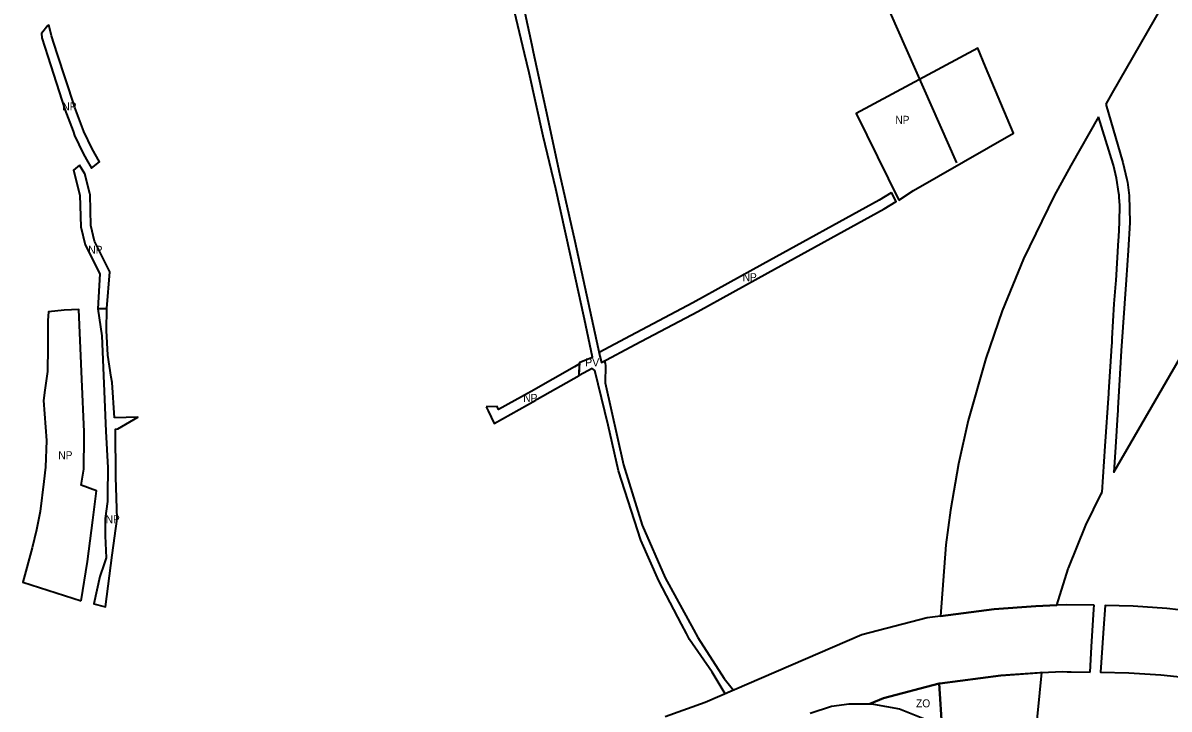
# Model space of a CAD drawing. Extents: x -650276 to -642489, y -1074311 to -1066720.
# Drawn here: x -649415 to -647696, y -1069108 to -1068079 of the extents above; entities that cross this region are included whole.
import ezdxf

# ---------------------------------------------------------------- set-up
doc = ezdxf.new("R2010")
doc.units = 0
doc.header["$LTSCALE"] = 4.8
for name, color, linetype, lineweight in [('15', 7, 'Continuous', 35), ('24', 7, 'Continuous', 35), ('25', 7, 'Continuous', 35), ('42', 7, 'Continuous', 35), ('48', 7, 'Continuous', 35), ('54', 7, 'Continuous', 35)]:
    doc.layers.add(name, color=color, linetype=linetype, lineweight=lineweight)
doc.layers.add('62', color=7, linetype='Continuous')

msp = doc.modelspace()

# ---------------------------------------------------------------- linework, layer by layer
at = {"layer": '15'}
for points in [[(-648668.92, -1068032.96), (-648651.89, -1068111.95), (-648649.74, -1068121.95), (-648644.73, -1068145.27), (-648630.99, -1068209.19), (-648610.14, -1068304.32), (-648587.39, -1068405.82), (-648559.91, -1068532.62), (-648549.84, -1068578.65), (-648547.25, -1068588.14), (-648542.93, -1068586.13), (-648541.74, -1068589.27)], [(-648349.419, -1069079.223), (-648362.06, -1069084.664), (-648381.44, -1069052.48), (-648415.29, -1069003.16), (-648419.78, -1068994.25), (-648427.21, -1068980.13), (-648461.22, -1068915.44), (-648488.09, -1068854.16), (-648521.92, -1068750.34), (-648537.29, -1068681.95), (-648557.4, -1068599.9), (-648559.44, -1068598.37), (-648561.49, -1068596.84), (-648580.66, -1068607.64), (-648579.97, -1068587.39), (-648560.79, -1068580.12), (-648572.95, -1068522.97), (-648573.96, -1068518.34), (-648594.38, -1068425.02), (-648615.87, -1068327.3), (-648634.84, -1068248.76), (-648655.88, -1068153.63), (-648662.71, -1068124.76), (-648677.61, -1068061.74)], [(-648541.74, -1068589.27), (-648541.25, -1068592.3), (-648541.89, -1068618.64), (-648514.35, -1068741.53), (-648486.25, -1068831.83), (-648451.76, -1068910.91), (-648409.15, -1068988.44), (-648402.76, -1069000.2), (-648363.11, -1069061.72), (-648349.419, -1069079.223)]]:
    msp.add_lwpolyline(points, dxfattribs=at)
at = {"layer": '24'}
for points in [[(-647864.531, -1068951.823), (-647895.901, -1068953.392), (-647958.168, -1068957.73), (-648038.596, -1068968.281), (-648038.759, -1068968.54)], [(-647808.28, -1068952.066), (-647850.043, -1068951.098), (-647864.531, -1068951.823)], [(-647814.401, -1069052.246), (-647812.34, -1069014.54), (-647808.67, -1068958.06), (-647808.28, -1068952.066)], [(-647629.424, -1068964.608), (-647699.561, -1068956.635), (-647749.978, -1068953.416), (-647792.01, -1068952.442), (-647794.21, -1068986.12), (-647796.13, -1069015.57), (-647798.631, -1069052.508), (-647756.441, -1069053.207), (-647708.401, -1069056.275), (-647511.94, -1069076.703)], [(-648038.759, -1068968.54), (-648038.746, -1068968.301), (-648058.764, -1068970.927), (-648156.739, -1068996.273), (-648392.002, -1069097.554), (-648451.865, -1069119.456)], [(-648040.705, -1069069.547), (-648039.666, -1069069.279), (-647948.18, -1069057.276), (-647886.615, -1069053.052), (-647856.541, -1069051.548), (-647848.615, -1069051.679), (-647842.888, -1069051.774), (-647814.401, -1069052.246)], [(-648234.22, -1069113.6), (-648202.46, -1069103.3), (-648175.65, -1069099.64), (-648144.866, -1069099.987), (-648124.327, -1069091.181), (-648040.705, -1069069.547)]]:
    msp.add_lwpolyline(points, dxfattribs=at)
at = {"layer": '25'}
msp.add_line((-648038.596, -1068968.281), (-647958.168, -1068957.73), dxfattribs=at)
for points in [[(-647685.819, -1068016.861), (-647781.346, -1068183.485), (-647791.055, -1068200.507)], [(-647791.055, -1068200.507), (-647765.22, -1068287.94), (-647759.412, -1068313.436)], [(-647801.797, -1068219.34), (-647843.6, -1068292.629), (-647868.214, -1068337.803), (-647914.339, -1068432.512), (-647946.187, -1068510.254), (-647971.074, -1068581.98), (-647997.27, -1068674.747), (-648011.775, -1068739.718), (-648023.914, -1068809.332), (-648030.73, -1068861.213), (-648038.596, -1068968.281)], [(-647771.413, -1068334.626), (-647774.94, -1068311.47), (-647779.55, -1068292.23), (-647780.07, -1068290.53), (-647801.797, -1068219.34)], [(-647768.02, -1068570.36), (-647770.94, -1068622.47), (-647772.85, -1068656.41), (-647773.08, -1068660.57), (-647773.4, -1068665.71), (-647776.5, -1068714.8), (-647778.95, -1068752.433), (-647675.054, -1068572.919), (-647535.844, -1068336.279), (-647464.94, -1068215.752)], [(-647759.412, -1068313.436), (-647758.45, -1068317.66), (-647756.09, -1068337.61), (-647754.99, -1068378.21), (-647757.41, -1068419.98), (-647760.22, -1068463.96), (-647768.02, -1068570.36)], [(-647796.173, -1068782.191), (-647791.77, -1068713.23), (-647786.47, -1068634.37), (-647786.32, -1068632.19), (-647781.85, -1068562.97), (-647781.55, -1068558.38), (-647781.13, -1068551.88), (-647778.24, -1068499.95), (-647775.82, -1068469.74), (-647775.52, -1068464.97), (-647771.74, -1068404.5), (-647771.47, -1068400.07), (-647770.12, -1068377.5), (-647769.92, -1068352.1), (-647770.81, -1068340.29), (-647771.05, -1068337.01), (-647771.413, -1068334.626)], [(-647846.989, -1068896.545), (-647820.883, -1068832.117), (-647797.632, -1068784.713), (-647796.173, -1068782.191)], [(-647958.168, -1068957.73), (-647895.901, -1068953.392), (-647864.531, -1068951.823), (-647847.197, -1068897.199), (-647847.034, -1068896.687), (-647846.989, -1068896.545)], [(-647948.18, -1069057.276), (-648039.666, -1069069.279), (-648040.705, -1069069.548), (-648036.291, -1069139.458)], [(-647886.615, -1069053.052), (-647889.927, -1069053.218), (-647948.18, -1069057.276)], [(-647893.553, -1069279.017), (-647896.67, -1069213.573), (-647896.362, -1069149.171), (-647886.615, -1069053.052)]]:
    msp.add_lwpolyline(points, dxfattribs=at)
at = {"layer": '42'}
msp.add_lwpolyline([(-648100.37, -1069107.1), (-648065.16, -1069121.12), (-648048.06, -1069130.81), (-648036.291, -1069139.458), (-648040.705, -1069069.547), (-648124.327, -1069091.181), (-648144.867, -1069099.987), (-648139.27, -1069100.05), (-648100.37, -1069107.1)], close=True, dxfattribs=at)
at = {"layer": '48'}
for points in [[(-649376.467, -1068081.552), (-649377.77, -1068082.44), (-649387.46, -1068094.51), (-649386.74, -1068101.31), (-649377.81, -1068129), (-649352.11, -1068208.65), (-649339.94, -1068241.13), (-649337.52, -1068247.59), (-649324.66, -1068274.3), (-649319.551, -1068283.382), (-649312.087, -1068296.653), (-649300.305, -1068287.002), (-649311.352, -1068267.362), (-649323.711, -1068241.693), (-649337.178, -1068205.751), (-649337.942, -1068203.713), (-649363.534, -1068124.395), (-649371.987, -1068098.185)], [(-648101.42, -1068344.28), (-648079.33, -1068330.03), (-647929.45, -1068244.16), (-647971.35, -1068144.48), (-647982.969, -1068116.575), (-648165.28, -1068214.465)], [(-649330.038, -1068291.976), (-649339.046, -1068299.359), (-649329.644, -1068336.779), (-649328.386, -1068384.468), (-649321.727, -1068411.472), (-649299.894, -1068454.728), (-649302.681, -1068507.363), (-649289.24, -1068506.8), (-649284.59, -1068451.76), (-649307.57, -1068406.23), (-649313.42, -1068382.51), (-649314.27, -1068336.41), (-649314.693, -1068334.727), (-649322.18, -1068304.93)], [(-648112.198, -1068333.037), (-648112.92, -1068333.424), (-648131.034, -1068344.388), (-648305.242, -1068440.3), (-648410.111, -1068498.408), (-648503.768, -1068547.914), (-648551.041, -1068573.16), (-648549.84, -1068578.65), (-648547.25, -1068588.14), (-648496.73, -1068561.16), (-648402.97, -1068511.6), (-648297.99, -1068453.43), (-648123.53, -1068357.38), (-648105.49, -1068346.46)], [(-649327.679, -1068945.222), (-649318.13, -1068886.42), (-649314.07, -1068855.33), (-649310.01, -1068824.2), (-649304.66, -1068780.33), (-649327.8, -1068771.82), (-649323.68, -1068748.06), (-649323.1, -1068699.28), (-649323.02, -1068692.1), (-649326.53, -1068612.89), (-649331.151, -1068508.557), (-649353.17, -1068509.48), (-649376.77, -1068511.96), (-649377.52, -1068525.1), (-649377.56, -1068564.89), (-649378.08, -1068601.24), (-649382.46, -1068629.34), (-649384.31, -1068644.92), (-649379.97, -1068704.98), (-649381.06, -1068744.69), (-649383.78, -1068766.6), (-649389.34, -1068811.43), (-649394.48, -1068838.89), (-649401.31, -1068865.78), (-649415.09, -1068917.1)], [(-648720.238, -1068654.205), (-648717.32, -1068660.24), (-648708.14, -1068679.23), (-648645.69, -1068644.27), (-648643.654, -1068643.123), (-648580.66, -1068607.64), (-648580.062, -1068590.087), (-648588.022, -1068594.571), (-648653.034, -1068631.191), (-648701.568, -1068658.36), (-648703.816, -1068653.711)]]:
    msp.add_lwpolyline(points, close=True, dxfattribs=at)
for points in [[(-649302.681, -1068507.363), (-649296.55, -1068548.09), (-649290.93, -1068690.93), (-649287.98, -1068745.74), (-649288.19, -1068786.39), (-649288.24, -1068796.6), (-649291.64, -1068821.88), (-649291.87, -1068848.02), (-649290.28, -1068880.82), (-649293.33, -1068889.65), (-649299.91, -1068908.66), (-649308.65, -1068950), (-649293.04, -1068953.81), (-649291.32, -1068954.23), (-649281.01, -1068876.69), (-649273.66, -1068822.58), (-649275.96, -1068759.73), (-649276.43, -1068688.29), (-649276.474, -1068687.673), (-649272.755, -1068687.618)], [(-649277.655, -1068670.983), (-649281.4, -1068618.05), (-649282.97, -1068610.04), (-649287.71, -1068577.14), (-649289.74, -1068540.2), (-649289.24, -1068506.8), (-649302.681, -1068507.363)], [(-649272.755, -1068687.618), (-649272.69, -1068687.58), (-649242.507, -1068669.925), (-649277.655, -1068670.983)]]:
    msp.add_lwpolyline(points, dxfattribs=at)
at = {"layer": '54'}
msp.add_lwpolyline([(-648383.36, -1067413.938), (-648264.607, -1067722.965), (-648014.937, -1068288.491)], dxfattribs=at)

# ---------------------------------------------------------------- texts
at = {"layer": '62', "width": 0.95}
for s, p in [('NP', (-649355.985, -1068209.967)), ('NP', (-648106.583, -1068230.041)), ('NP', (-649316.985, -1068424.967)), ('NP', (-648335.583, -1068466.041)), ('NP', (-648664.583, -1068647.041)), ('NP', (-649361.985, -1068732.967)), ('NP', (-649290.985, -1068828.967)), ('ZO', (-648075.473, -1069105.058))]:
    msp.add_text(s, height=12, dxfattribs=at).set_placement(p)
at = {"layer": '62'}
msp.add_text('PV', height=12, dxfattribs=at).set_placement((-648571.984, -1068593.692))

doc.saveas('drawing.dxf')
